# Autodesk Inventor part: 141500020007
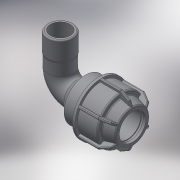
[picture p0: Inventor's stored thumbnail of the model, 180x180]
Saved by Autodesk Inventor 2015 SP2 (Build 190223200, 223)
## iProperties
Created: 2017-08
Part Number: 141500020007
Material: Generic
Description: L.14 90° ELBOW FEMALE ADAPTOR (SILVER) 20-3/4"
Document SubType Name: Modeling
Designer: KIM
Density: 1 g/cm^3
Appearance: Default
Author: KIM
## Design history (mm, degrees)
derived "141500.ipt"
feature "Solid1::141500.ipt"
feature "Solid2::141500.ipt"
tag "TaggingFeature1"
body "Solid1"
body "Solid2"
other parameters: "d2" = 44, "d4" = 15 deg, "d5" = 29.04, "d6" = 9.5832, "d10" = 42, "d16" = 20.4, "d17" = 2.2, "d22" = 32, "d24" = 2.2, "d25" = 37.8, "d26" = 31.5, "d27" = 2.2, "d28" = 135 deg, "d29" = 1.32, "d31" = 1, "d46" = 150 deg, "d49" = 2.1, "d50" = 0, "d58" = 0.6, "d61" = 360 deg, "d63" = 18, "d94" = 42, "d95" = 24.117, "d96" = 31.3521, "d97" = 18, "d98" = 19.2936, "d99" = 28.21689, "d100" = 135 deg, "d108" = 1, "d112" = 23.4, "d113" = 56, "d114" = 44.88, "d115" = 28.21689, "d116" = 45 deg, "d117" = 0, "d118" = 0, "G_" = 24.117, "E_" = 42, "A_" = 56, "l_" = 44, "l_2" = 18, "A_1" = 42
